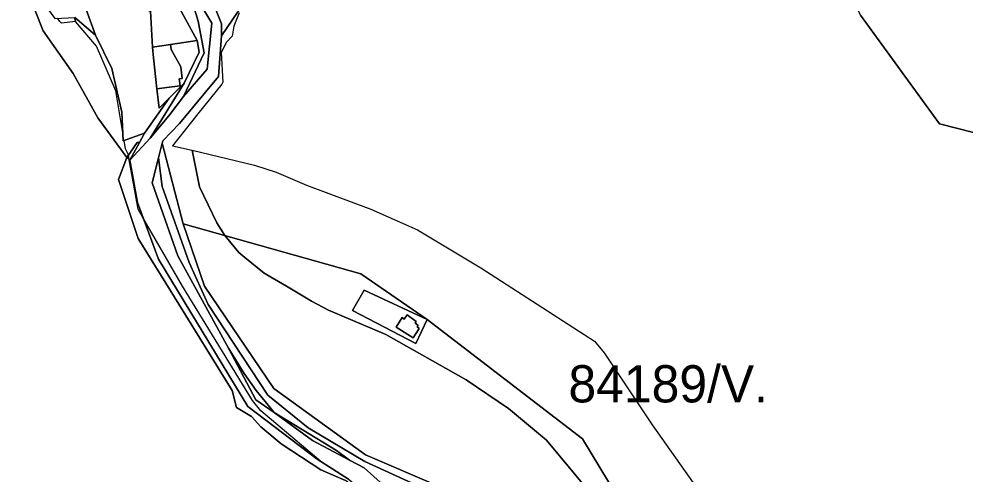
# Model space of a CAD drawing. Extents: x -477304 to -465429, y -1159113 to -1149210.
# Drawn here: x -473381.9 to -473001.2, y -1152924.3 to -1152741 of the extents above; entities that cross this region are included whole.
import ezdxf

# ---------------------------------------------------------------- set-up
doc = ezdxf.new("R2010")
doc.units = 0
for name, color, linetype in [('BPEJ_s', 7, 'Continuous'), ('ostatni_s', 7, 'Continuous'), ('PUPFL_s', 7, 'Continuous'), ('trav_porost_s', 7, 'Continuous'), ('voda_s', 7, 'Continuous')]:
    doc.layers.add(name, color=color, linetype=linetype)

msp = doc.modelspace()

# ---------------------------------------------------------------- linework, layer by layer
at = {"layer": 'BPEJ_s'}
for points in [[(-473293.24, -1152738.65), (-473295.37, -1152743.97), (-473296.01, -1152748.01), (-473298.35, -1152750.35), (-473300.48, -1152754.61), (-473299.84, -1152766.52), (-473300.26, -1152767.37), (-473309.84, -1152779.29), (-473320.12, -1152792.09), (-473312.11, -1152793.88), (-473287.07, -1152799.93), (-473278.34, -1152802.7), (-473266.22, -1152808.01), (-473240.26, -1152817.59), (-473221.53, -1152825.89), (-473196, -1152841.21), (-473150.25, -1152870.78), (-473146.42, -1152875.47), (-473127.06, -1152904.4), (-473106.63, -1152933.34)], [(-473293.24, -1152738.65), (-473295.37, -1152743.97), (-473296.01, -1152748.01), (-473298.35, -1152750.35), (-473300.48, -1152754.61), (-473299.84, -1152766.52), (-473300.26, -1152767.37)], [(-473359.45, -1152740.48), (-473359.28, -1152741.36), (-473359.13, -1152742.11), (-473364.73, -1152742.69), (-473365.37, -1152742.05), (-473366.35, -1152740.77)], [(-473251.75, -1152924.83), (-473260.05, -1152919.51), (-473260.38, -1152919.23), (-473284.52, -1152898.87), (-473287.92, -1152894.62), (-473316.01, -1152848.66), (-473331.97, -1152820.92), (-473333.88, -1152817.59), (-473337.51, -1152797.71), (-473337.85, -1152795.88), (-473337.89, -1152795.66), (-473337.92, -1152795.46), (-473338.99, -1152793.33), (-473339.54, -1152789.98), (-473339.87, -1152790.1), (-473340.04, -1152786.89), (-473342.82, -1152769.93), (-473350.69, -1152752.05), (-473359.13, -1152742.11), (-473364.73, -1152742.69), (-473365.37, -1152742.05), (-473366.35, -1152740.77)], [(-473337.92, -1152795.46), (-473338.99, -1152793.33), (-473339.54, -1152789.98), (-473339.87, -1152790.1), (-473340.04, -1152786.89), (-473342.82, -1152769.93), (-473350.69, -1152752.05), (-473359.13, -1152742.11), (-473359.28, -1152741.36), (-473359.45, -1152740.48)], [(-473300.26, -1152767.37), (-473309.84, -1152779.29), (-473320.12, -1152792.09), (-473312.11, -1152793.88), (-473309.2, -1152808.65), (-473302.18, -1152823.12), (-473298.96, -1152828.26), (-473293.45, -1152835.04), (-473290.93, -1152837.09), (-473283.24, -1152843.34), (-473274.18, -1152848.67), (-473264.09, -1152854.61), (-473257.28, -1152858.23), (-473234.3, -1152868.02), (-473201.96, -1152886.32), (-473184.93, -1152897.81), (-473169.61, -1152910.57), (-473145.78, -1152939.3)], [(-473251.75, -1152924.83), (-473260.05, -1152919.51), (-473260.38, -1152919.23), (-473284.52, -1152898.87), (-473287.92, -1152894.62), (-473316.01, -1152848.66), (-473331.97, -1152820.92), (-473333.88, -1152817.59), (-473337.51, -1152797.71), (-473337.85, -1152795.88), (-473337.89, -1152795.66), (-473337.92, -1152795.46)], [(-473145.78, -1152939.3), (-473169.61, -1152910.57), (-473184.93, -1152897.81), (-473201.96, -1152886.32), (-473234.3, -1152868.02), (-473257.28, -1152858.23), (-473264.09, -1152854.61), (-473274.18, -1152848.67), (-473283.24, -1152843.34), (-473290.93, -1152837.09), (-473293.45, -1152835.04), (-473298.96, -1152828.26), (-473302.18, -1152823.12), (-473309.2, -1152808.65), (-473312.11, -1152793.88), (-473287.07, -1152799.93), (-473278.34, -1152802.7), (-473266.22, -1152808.01), (-473240.26, -1152817.59), (-473221.53, -1152825.89), (-473196, -1152841.21), (-473150.25, -1152870.78), (-473146.42, -1152875.47), (-473127.06, -1152904.4), (-473106.63, -1152933.34)]]:
    msp.add_lwpolyline(points, dxfattribs=at)
at = {"layer": 'ostatni_s'}
for points in [[(-473314.8, -1152725.09), (-473309.75, -1152741.94), (-473307.35, -1152754.74), (-473315.65, -1152772.24), (-473321.55, -1152780.04), (-473329.13, -1152789.02), (-473315.43, -1152766.92), (-473309.31, -1152754.48), (-473310.15, -1152749.67), (-473318.05, -1152735.26)], [(-473214.29, -1152932.19), (-473242.63, -1152919.25), (-473265.48, -1152905.6), (-473281.74, -1152892.46), (-473305.72, -1152856.02), (-473313.39, -1152839.13), (-473324.29, -1152808.46), (-473325.7, -1152796.96), (-473324.18, -1152791.02), (-473315.8, -1152823.53), (-473307.22, -1152848.58), (-473279.3, -1152889.81), (-473242.38, -1152916.54), (-473212.99, -1152929.2)]]:
    msp.add_lwpolyline(points, dxfattribs=at)
for points in [[(-473315.65, -1152772.24), (-473307.35, -1152754.74), (-473309.75, -1152741.94), (-473314.8, -1152725.09), (-473304.28, -1152742.75), (-473306.07, -1152761.24)], [(-473320.85, -1152751.31), (-473320.62, -1152753.33), (-473316.72, -1152760.37), (-473316.13, -1152764.98), (-473317.34, -1152765.14), (-473316.98, -1152767.91), (-473321.29, -1152768.52), (-473326.38, -1152769.14), (-473327.78, -1152756.7), (-473328.11, -1152752.43)], [(-473315.43, -1152766.92), (-473329.13, -1152789.02), (-473337.29, -1152797.93), (-473333.33, -1152790.73), (-473331.3, -1152787.03), (-473321.43, -1152772.99)], [(-473313.39, -1152839.13), (-473305.72, -1152856.02), (-473281.74, -1152892.46), (-473265.48, -1152905.6), (-473242.63, -1152919.25), (-473214.29, -1152932.19), (-473201.98, -1152946.69), (-473196.04, -1152960.33), (-473199.45, -1152958.39), (-473204.41, -1152952.98), (-473221.29, -1152939.1), (-473235.18, -1152928.77), (-473243.01, -1152921.71), (-473248.82, -1152918.63), (-473254.05, -1152914.74), (-473279.2, -1152899.45), (-473286.45, -1152890.59), (-473291.24, -1152883.84), (-473297.51, -1152873.65), (-473318, -1152836.41), (-473328.29, -1152807.09), (-473325.7, -1152796.96), (-473324.29, -1152808.46)], [(-473243, -1152850.17), (-473247.66, -1152858.37), (-473222.2, -1152871.75), (-473217.56, -1152862.11), (-473155.08, -1152910.13), (-473106.29, -1152990.89), (-473108.13, -1153005.67), (-473128.13, -1153027.6), (-473143.38, -1153044.31), (-473154.55, -1153016.3), (-473176.7, -1152980.7), (-473193.51, -1152959.46), (-473199.49, -1152945.03), (-473212.99, -1152929.2), (-473242.38, -1152916.54), (-473279.3, -1152889.81), (-473307.22, -1152848.58), (-473315.8, -1152823.53), (-473244.36, -1152843.64), (-473217.56, -1152862.11)], [(-473243, -1152850.17), (-473217.56, -1152862.11), (-473222.2, -1152871.75), (-473247.66, -1152858.37)], [(-473221.69, -1152865.06), (-473220.81, -1152865.61), (-473223.24, -1152869.49), (-473230.1, -1152865.15), (-473227.63, -1152861.29), (-473226.81, -1152861.86), (-473225.66, -1152860.22), (-473221.97, -1152862.8), (-473222.49, -1152863.54), (-473221.24, -1152864.41)], [(-473226.81, -1152861.86), (-473227.63, -1152861.29), (-473230.1, -1152865.15), (-473223.24, -1152869.49), (-473220.81, -1152865.61), (-473221.69, -1152865.06), (-473221.24, -1152864.41), (-473222.49, -1152863.54), (-473221.97, -1152862.8), (-473225.66, -1152860.22)]]:
    msp.add_lwpolyline(points, close=True, dxfattribs=at)
at = {"layer": 'PUPFL_s'}
for points in [[(-473016.38, -1152623.9), (-472865.83, -1152635.64), (-472855.55, -1152769.89), (-472853.16, -1152808.52), (-472899.43, -1152806.72), (-472950.49, -1152798.87), (-473011.45, -1152783.25), (-473043.28, -1152739.47), (-473083.55, -1152653.86)], [(-473300.42, -1152747.86), (-473300.33, -1152743.04), (-473308.36, -1152722.56), (-473286.02, -1152708.39), (-473284.2, -1152723.81)], [(-473381.88, -1152721.04), (-473367.39, -1152740.81), (-473359.38, -1152740.48), (-473351.13, -1152747.56), (-473344.52, -1152760.98), (-473340.49, -1152778.59), (-473339.87, -1152790.1), (-473331.3, -1152787.03), (-473333.33, -1152790.73), (-473334.29, -1152790.85), (-473338.48, -1152796.77), (-473350.09, -1152780.92), (-473360.01, -1152763.05), (-473372.17, -1152745.88)]]:
    msp.add_lwpolyline(points, close=True, dxfattribs=at)
for points in [[(-473381.88, -1152721.04), (-473372.17, -1152745.88), (-473360.01, -1152763.05), (-473350.09, -1152780.92), (-473338.48, -1152796.77), (-473341.8, -1152805.68), (-473333.96, -1152829.42), (-473319.24, -1152853.07), (-473296.04, -1152890.62), (-473294.31, -1152897.45), (-473288.25, -1152901.13), (-473284.52, -1152905.27), (-473276.37, -1152912.11), (-473260.46, -1152922.55), (-473250.52, -1152926.81)], [(-472962.85, -1152969.01), (-473001.34, -1152978.85), (-473028.57, -1152989.07), (-473051.84, -1152985.25), (-473081.12, -1152990.24), (-473106.29, -1152990.89), (-473155.08, -1152910.13), (-473217.56, -1152862.11), (-473244.36, -1152843.64), (-473315.8, -1152823.53), (-473324.18, -1152791.02), (-473323.92, -1152790.07), (-473317.27, -1152783.1), (-473301.51, -1152764.2), (-473300.42, -1152747.86), (-473284.2, -1152723.81)], [(-473043.28, -1152739.47), (-473011.45, -1152783.25), (-472950.49, -1152798.87), (-472899.43, -1152806.72), (-472853.16, -1152808.52), (-472749.46, -1152789.75), (-472604.44, -1152737.46)]]:
    msp.add_lwpolyline(points, dxfattribs=at)
at = {"layer": 'trav_porost_s'}
for points in [[(-473356.62, -1152732.34), (-473351.13, -1152747.56), (-473359.38, -1152740.48)], [(-473318.05, -1152735.26), (-473310.15, -1152749.67), (-473320.85, -1152751.31), (-473328.11, -1152752.43), (-473328.96, -1152737.93)]]:
    msp.add_lwpolyline(points, dxfattribs=at)
for points in [[(-473340.49, -1152778.59), (-473344.52, -1152760.98), (-473351.13, -1152747.56), (-473356.62, -1152732.34), (-473347.05, -1152732.79), (-473328.96, -1152737.93), (-473328.11, -1152752.43), (-473327.78, -1152756.7), (-473326.38, -1152769.14), (-473325.5, -1152776.9), (-473321.43, -1152772.99), (-473331.3, -1152787.03), (-473339.87, -1152790.1)], [(-473317.34, -1152765.14), (-473316.13, -1152764.98), (-473316.72, -1152760.37), (-473320.62, -1152753.33), (-473320.85, -1152751.31), (-473310.15, -1152749.67), (-473309.31, -1152754.48), (-473315.43, -1152766.92), (-473321.43, -1152772.99), (-473325.5, -1152776.9), (-473326.38, -1152769.14), (-473321.29, -1152768.52), (-473316.98, -1152767.91)]]:
    msp.add_lwpolyline(points, close=True, dxfattribs=at)
at = {"layer": 'voda_s'}
for points in [[(-473308.36, -1152722.56), (-473300.33, -1152743.04), (-473300.42, -1152747.86), (-473301.51, -1152764.2), (-473317.27, -1152783.1), (-473323.92, -1152790.07), (-473324.18, -1152791.02), (-473325.7, -1152796.96), (-473328.29, -1152807.09), (-473318, -1152836.41), (-473297.51, -1152873.65), (-473286.59, -1152894.36), (-473279.2, -1152899.45)], [(-473249.22, -1152926.34), (-473261.81, -1152918.32), (-473289.72, -1152897.07), (-473325.73, -1152837.76), (-473334.17, -1152814.97), (-473337.29, -1152797.93), (-473329.13, -1152789.02), (-473321.55, -1152780.04), (-473315.65, -1152772.24), (-473306.07, -1152761.24), (-473304.28, -1152742.75), (-473314.8, -1152725.09)], [(-473279.2, -1152899.45), (-473263.69, -1152910.74), (-473248.82, -1152918.63), (-473243.01, -1152921.71), (-473235.18, -1152928.77)]]:
    msp.add_lwpolyline(points, dxfattribs=at)
for points in [[(-473334.29, -1152790.85), (-473333.33, -1152790.73), (-473337.29, -1152797.93), (-473338.48, -1152796.77)], [(-473260.46, -1152922.55), (-473276.37, -1152912.11), (-473284.52, -1152905.27), (-473288.25, -1152901.13), (-473294.31, -1152897.45), (-473296.04, -1152890.62), (-473319.24, -1152853.07), (-473333.96, -1152829.42), (-473341.8, -1152805.68), (-473338.48, -1152796.77), (-473337.29, -1152797.93), (-473334.17, -1152814.97), (-473325.73, -1152837.76), (-473289.72, -1152897.07), (-473261.81, -1152918.32), (-473249.22, -1152926.34), (-473219.97, -1152949.27), (-473222.65, -1152950.83), (-473225.72, -1152947.78), (-473230.71, -1152942.82), (-473234.06, -1152939.49), (-473250.52, -1152926.81)], [(-473286.45, -1152890.59), (-473279.2, -1152899.45), (-473286.59, -1152894.36), (-473297.51, -1152873.65), (-473291.24, -1152883.84)], [(-473279.2, -1152899.45), (-473254.05, -1152914.74), (-473248.82, -1152918.63), (-473263.69, -1152910.74)]]:
    msp.add_lwpolyline(points, close=True, dxfattribs=at)

# ---------------------------------------------------------------- texts
at = {"layer": 'BPEJ_s'}
msp.add_text('84189/V.', height=15, dxfattribs=at).set_placement((-473160.76, -1152895.43))

doc.saveas('drawing.dxf')
